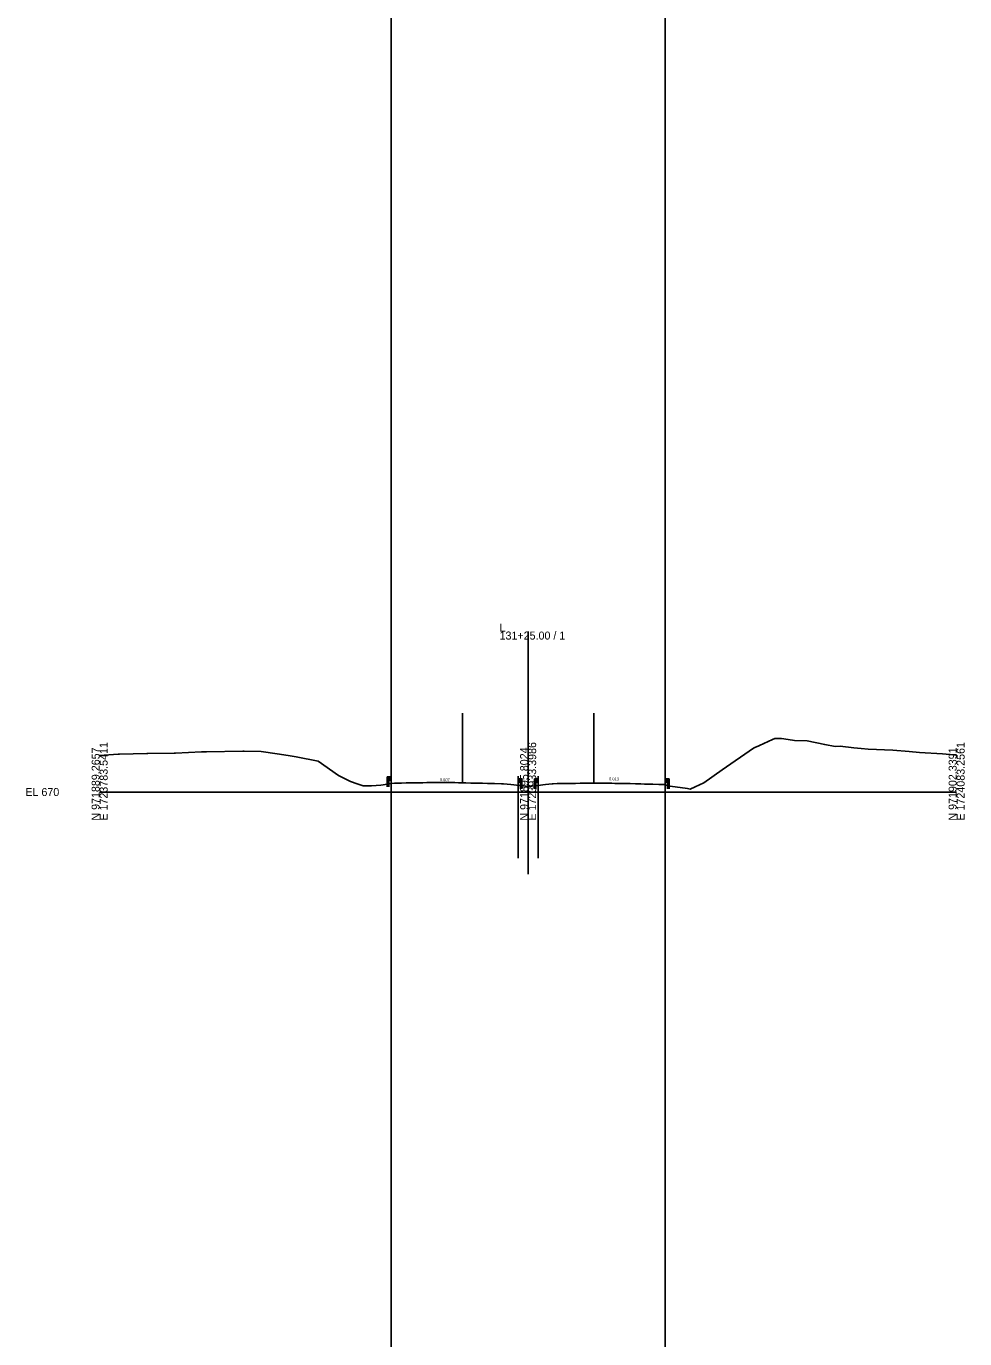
# Model space of a CAD drawing. Extents: x -26 to 303, y -29 to 15026.
# Drawn here: x -25.7 to 302.8, y 1808.7 to 2268 of the extents above; entities that cross this region are included whole.
import ezdxf

# ---------------------------------------------------------------- set-up
doc = ezdxf.new("R2010")
doc.units = 0
for name, color, linetype in [('Exist Cross Section Cell', 7, 'Continuous'), ('Exist XS Center Line Elevation Label', 7, 'Continuous'), ('Exist XS Ground Line', 7, 'Continuous'), ('Prop XS Ditch Standard Text', 7, 'Continuous'), ('Scratch_Level_0', 7, 'Continuous'), ('Typical Guardrail CELL', 7, 'Continuous')]:
    doc.layers.add(name, color=color, linetype=linetype)

msp = doc.modelspace()

# ---------------------------------------------------------------- linework, layer by layer
at = {"layer": 'Exist Cross Section Cell'}
for p, q in [((150, 2000), (150, 2056.16)), ((0, 2000), (150, 2000)), ((150, 2000), (300, 2000))]:
    msp.add_line(p, q, dxfattribs=at)
at = {"layer": 'Exist XS Ground Line'}
msp.add_lwpolyline([(0, 2012.83), (6.48, 2013.21), (6.91, 2013.23), (16.5, 2013.43), (16.88, 2013.43), (26.09, 2013.65), (26.5, 2013.66), (35.68, 2014.08), (36.5, 2014.09), (37.39, 2014.12), (50.1, 2014.34), (50.56, 2014.3), (56.52, 2014.23), (62.11, 2013.37), (66.04, 2012.74), (68.85, 2012.29), (76.54, 2010.77), (83.64, 2005.8), (87.84, 2003.69), (90.19, 2002.91), (92.26, 2002.17), (94.58, 2002.14), (95.2, 2002.13), (98.44, 2002.46), (102.27, 2003.03), (103.17, 2003.08), (104.93, 2003.13), (105.65, 2003.16), (107.34, 2003.21), (108.16, 2003.23), (109.75, 2003.24), (110.66, 2003.25), (111.15, 2003.26), (111.82, 2003.27), (113.18, 2003.27), (114.57, 2003.28), (115.67, 2003.28), (116.88, 2003.29), (118.17, 2003.3), (119.49, 2003.3), (120.66, 2003.3), (122.01, 2003.3), (123.07, 2003.3), (124.38, 2003.28), (125.65, 2003.25), (127.32, 2003.21), (128.15, 2003.19), (129.95, 2003.15), (130.65, 2003.14), (132.6, 2003.09), (133.18, 2003.08), (134.03, 2003.05), (135.74, 2003.01), (137.65, 2002.96), (138.21, 2002.95), (140.62, 2002.89), (141.01, 2002.88), (141.35, 2002.87), (143.93, 2002.58), (146.98, 2002.25), (150.21, 2001.93), (153.41, 2002.26), (156.1, 2002.6), (158.46, 2002.89), (158.76, 2002.9), (160.13, 2002.93), (160.68, 2002.94), (162.47, 2002.97), (163.2, 2002.99), (163.81, 2003), (164.52, 2003.02), (165.1, 2003.03), (165.7, 2003.03), (166.6, 2003.04), (168.22, 2003.06), (169.72, 2003.07), (170.73, 2003.08), (171.84, 2003.09), (173.22, 2003.1), (174.51, 2003.11), (175.74, 2003.11), (176.79, 2003.11), (177.3, 2003.11), (178.23, 2003.09), (179.29, 2003.07), (180.72, 2003.04), (182.29, 2003.01), (183.21, 2003), (184.06, 2002.98), (185.72, 2002.95), (187.53, 2002.91), (188.21, 2002.9), (189.49, 2002.87), (190.72, 2002.81), (192.78, 2002.77), (193.23, 2002.76), (193.64, 2002.75), (195.76, 2002.69), (196.34, 2002.68), (197.25, 2002.65), (197.68, 2002.63), (198.17, 2002.43), (199.69, 2002.07), (205.81, 2001.18), (206.67, 2001.03), (208.44, 2001.85), (211.48, 2003.22), (217.95, 2007.74), (228.86, 2015.41), (229.64, 2015.74), (230.48, 2016.1), (231.04, 2016.25), (235.55, 2018.41), (236.34, 2018.71), (238.64, 2018.72), (239.52, 2018.66), (243.19, 2018.07), (247.66, 2017.96), (253.85, 2016.59), (257.53, 2015.99), (259.24, 2016), (263.97, 2015.45), (266.53, 2015.21), (269.06, 2015.02), (277.7, 2014.64), (283.33, 2014.15), (287.04, 2013.79), (295, 2013.35), (299.04, 2013.06), (300, 2012.99)], dxfattribs=at)
at = {"layer": 'Scratch_Level_0'}
for p, q in [((102, 15009.56), (102, -28.7)), ((198, 15009.56), (198, -28.7)), ((127, 2003.22), (127, 2027.58)), ((173, 2003.1), (173, 2027.58)), ((127, 2003.22), (116.88, 2003.29)), ((146.46, 2005.5), (146.46, 1976.8)), ((153.54, 2005.5), (153.54, 1976.8)), ((173, 2003.1), (187.53, 2002.91)), ((150, 2000), (150, 1971.3))]:
    msp.add_line(p, q, dxfattribs=at)
at = {"layer": 'Typical Guardrail CELL'}
for p, q in [((101.18, 2005.28), (100.68, 2005.28)), ((100.68, 2005.28), (100.68, 2002.8)), ((101.18, 2002.8), (100.68, 2002.8)), ((100.68, 2002.8), (100.68, 2001.79)), ((101.18, 2005.28), (101.18, 2002.8)), ((101.18, 2005.28), (101.68, 2005.28)), ((101.18, 2004.12), (101.68, 2004.12)), ((101.18, 2002.8), (101.18, 2001.79)), ((101.68, 2005.28), (101.68, 2004.12)), ((101.68, 2005.28), (101.97, 2005.08)), ((101.68, 2004.75), (101.97, 2004.95)), ((101.68, 2004.7), (101.68, 2004.75)), ((101.68, 2004.7), (101.68, 2004.66)), ((101.68, 2004.66), (101.97, 2004.45)), ((101.68, 2004.12), (101.97, 2004.33)), ((146.78, 2004.66), (146.49, 2004.46)), ((146.78, 2004.13), (146.49, 2004.33)), ((146.78, 2004.03), (146.49, 2003.83)), ((146.78, 2003.5), (146.49, 2003.7)), ((147.28, 2004.66), (146.78, 2004.66)), ((146.78, 2004.66), (146.78, 2003.5)), ((146.78, 2004.08), (146.78, 2004.13)), ((146.78, 2004.08), (146.78, 2004.03)), ((147.28, 2003.5), (146.78, 2003.5)), ((147.28, 2004.66), (147.28, 2002.17)), ((147.28, 2004.66), (147.78, 2004.66)), ((147.78, 2004.66), (147.78, 2002.17)), ((152.72, 2004.62), (152.22, 2004.62)), ((152.22, 2004.62), (152.22, 2002.14)), ((152.72, 2004.62), (152.72, 2002.14)), ((152.72, 2004.62), (153.22, 2004.62)), ((152.72, 2003.46), (153.22, 2003.46)), ((153.22, 2004.62), (153.22, 2003.46)), ((153.22, 2004.62), (153.51, 2004.42)), ((153.22, 2004.09), (153.51, 2004.29)), ((153.22, 2004.04), (153.22, 2004.09)), ((153.22, 2004.04), (153.22, 2004)), ((153.22, 2004), (153.51, 2003.79)), ((153.22, 2003.46), (153.51, 2003.67)), ((198.32, 2004.64), (198.03, 2004.44)), ((198.32, 2004.11), (198.03, 2004.31)), ((198.32, 2004.01), (198.03, 2003.81)), ((198.32, 2003.48), (198.03, 2003.68)), ((198.82, 2004.64), (198.32, 2004.64)), ((198.32, 2004.64), (198.32, 2003.48)), ((198.32, 2004.06), (198.32, 2004.11)), ((198.32, 2004.06), (198.32, 2004.01)), ((198.82, 2003.48), (198.32, 2003.48)), ((198.82, 2004.64), (198.82, 2002.16)), ((198.82, 2004.64), (199.32, 2004.64)), ((199.32, 2004.64), (199.32, 2002.16)), ((147.28, 2002.17), (147.78, 2002.17)), ((147.28, 2002.17), (147.28, 2001.16)), ((147.78, 2002.17), (147.78, 2001.16)), ((152.72, 2002.14), (152.22, 2002.14)), ((152.22, 2002.14), (152.22, 2001.13)), ((152.72, 2002.14), (152.72, 2001.13)), ((198.82, 2002.16), (199.32, 2002.16)), ((198.82, 2002.16), (198.82, 2001.15)), ((199.32, 2002.16), (199.32, 2001.15))]:
    msp.add_line(p, q, dxfattribs=at)
for centre, start, end in [((101.92, 2005.02), 304.9888, 54.997), ((101.92, 2004.39), 304.9634, 54.9941), ((146.54, 2004.39), 125.003, 235.0112), ((146.54, 2003.76), 125.0059, 235.0366), ((153.46, 2004.36), 304.9888, 54.997), ((153.46, 2003.73), 304.9634, 54.9941), ((198.08, 2004.37), 125.003, 235.0112), ((198.08, 2003.75), 125.0059, 235.0366)]:
    msp.add_arc(centre, 0.0776, start, end, dxfattribs=at)

# ---------------------------------------------------------------- texts
at = {"layer": 'Exist Cross Section Cell'}
for s, p in [('L', (140, 2056.16)), ('131+25.00 / 1', (140, 2053.36)), ('EL 670', (-26, 1998.6))]:
    msp.add_text(s, height=2.8, dxfattribs=at).set_placement(p)
for s, p in [('E 1723783.5411', (2.8, 1990)), ('E 1723933.3986', (152.8, 1990)), ('E 1724083.2561', (302.8, 1990)), ('N 971889.2657', (0, 1990)), ('N 971895.8024', (150, 1990)), ('N 971902.3391', (300, 1990))]:
    msp.add_text(s, height=2.8, rotation=90, dxfattribs=at).set_placement(p)
at = {"layer": 'Exist XS Center Line Elevation Label'}
msp.add_text('671.95', height=0.18, dxfattribs=at).set_placement((149.64, 2001.46))
at = {"layer": 'Prop XS Ditch Standard Text'}
for s, rotation, p in [('0.007', 359.5792, (119.08, 2003.82)), ('0.013', 359.266, (178.31, 2004.11))]:
    msp.add_text(s, height=1, rotation=rotation, dxfattribs=at).set_placement(p)

doc.saveas('drawing.dxf')
